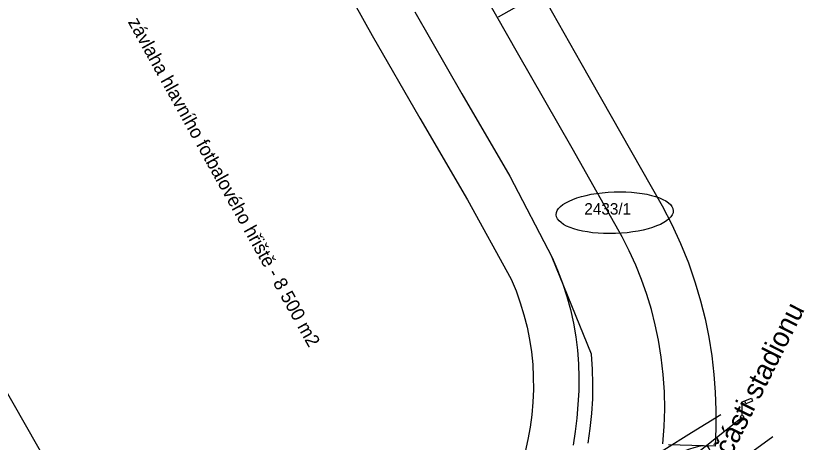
# Model space of a CAD drawing. Extents: x -483721 to -481876, y -1129170 to -1127366.
# Drawn here: x -482396.9 to -482279.7, y -1128190 to -1128126.6 of the extents above; entities that cross this region are included whole.
import ezdxf

# ---------------------------------------------------------------- set-up
doc = ezdxf.new("R2010")
doc.units = 0
for name, color, linetype in [('3 Betonove Plochy', 7, 'Continuous'), ('4 Komunikace', 7, 'Continuous'), ('4 Obrubniky', 7, 'Continuous'), ('kresba', 7, 'Continuous'), ('oblast', 7, 'Continuous'), ('OSTATNI', 7, 'Continuous'), ('Parcelní čísla', 7, 'Continuous'), ('u_návrh_popis', 7, 'Continuous'), ('u_SO_POPIS_1000', 7, 'Continuous')]:
    doc.layers.add(name, color=color, linetype=linetype)

# ---------------------------------------------------------------- blocks, each defined once
blk = doc.blocks.new('LAMPA')
for p, q in [((0, 4.55), (2.79, 5.63)), ((1.17, 3.98), (0.84, 4.87)), ((3.13, 4.71), (1.17, 3.98)), ((2.79, 5.63), (3.13, 4.71)), ((0, 0.52), (0, 4.55))]:
    blk.add_line(p, q)
blk.add_circle((0, 0.02), 0.5)

msp = doc.modelspace()

# ---------------------------------------------------------------- linework, layer by layer
at = {"layer": '3 Betonove Plochy'}
msp.add_lwpolyline([(-482325.12, -1128126.82), (-482318.79, -1128123.2), (-482312.89, -1128133.61), (-482306.96, -1128144.09), (-482300.81, -1128154.85), (-482299.38, -1128157.61), (-482298.08, -1128160.45), (-482296.92, -1128163.34), (-482295.9, -1128166.29), (-482295.11, -1128168.95), (-482294.45, -1128171.65), (-482293.9, -1128174.37), (-482293.46, -1128177.12), (-482293.14, -1128179.88), (-482292.94, -1128182.54), (-482292.84, -1128185.21), (-482292.85, -1128187.88), (-482292.96, -1128190.54), (-482299.89, -1128190.33)], dxfattribs=at)
at = {"layer": '4 Komunikace'}
for points in [[(-482300.71, -1128190.19), (-482300.5, -1128187.62), (-482300.42, -1128185.05), (-482300.47, -1128182.47), (-482300.65, -1128179.91), (-482300.94, -1128177.35), (-482301.36, -1128174.81), (-482301.84, -1128172.52), (-482302.42, -1128170.26), (-482303.09, -1128168.02), (-482303.87, -1128165.82), (-482304.74, -1128163.65), (-482305.7, -1128161.52), (-482306.76, -1128159.44), (-482314.2, -1128146.29), (-482322.32, -1128132.12), (-482330.27, -1128118.08)], [(-482337.58, -1128126.06), (-482330.59, -1128138.24), (-482323.44, -1128150.46), (-482317.17, -1128162.55), (-482316.35, -1128164.43), (-482315.62, -1128166.35), (-482314.98, -1128168.3), (-482314.44, -1128170.27), (-482313.99, -1128172.27), (-482313.63, -1128174.29), (-482313.38, -1128176.29), (-482313.24, -1128178.31), (-482313.18, -1128180.33), (-482313.22, -1128182.35), (-482313.33, -1128184.36), (-482313.51, -1128186.38), (-482313.75, -1128188.39), (-482314.06, -1128190.39)], [(-482311.82, -1128190.08), (-482311.49, -1128187.9), (-482311.26, -1128185.7), (-482311.13, -1128183.5), (-482311.1, -1128181.3), (-482311.17, -1128179.1), (-482311.33, -1128176.9), (-482317.17, -1128162.55)]]:
    msp.add_lwpolyline(points, dxfattribs=at)
at = {"layer": '4 Obrubniky'}
for points in [[(-482350.84, -1128117.09), (-482343.92, -1128129.57), (-482336.82, -1128141.83), (-482329.75, -1128153.97), (-482323.25, -1128165.76), (-482322.53, -1128167.49), (-482321.9, -1128169.26), (-482321.35, -1128171.05), (-482320.88, -1128172.86), (-482320.51, -1128174.7), (-482320.23, -1128176.55), (-482320.05, -1128178.41), (-482319.96, -1128180.27), (-482319.95, -1128182.14), (-482320.03, -1128184.01), (-482320.19, -1128185.87), (-482320.44, -1128187.72), (-482320.76, -1128189.57), (-482321.17, -1128191.39)], [(-482391.56, -1128194.16), (-482399.3, -1128180.6)]]:
    msp.add_lwpolyline(points, dxfattribs=at)
at = {"layer": 'kresba'}
for points in [[(-482386.87, -1128244.71), (-482337.34, -1128245.3), (-482304.59, -1128221.02), (-482292.62, -1128190.48), (-482292.12, -1128185.83), (-482386.87, -1128244.71), (-482292.12, -1128185.83)], [(-482371.94, -1128252.14), (-482352.87, -1128253.17), (-482333.7, -1128247.75), (-482316.47, -1128237.78), (-482302, -1128223.19), (-482292.54, -1128205.83), (-482288.95, -1128186.24), (-482371.94, -1128252.14), (-482288.95, -1128186.24)], [(-482371.94, -1128252.14), (-482347.59, -1128254.37), (-482324.64, -1128248.35), (-482320.83, -1128246.15), (-482296.38, -1128222.8), (-482288.05, -1128206.72), (-482284.38, -1128189.12), (-482371.94, -1128252.14), (-482284.38, -1128189.12)]]:
    msp.add_open_spline(points, degree=3, dxfattribs=at)
at = {"layer": 'oblast'}
msp.add_ellipse((-482307.86, -1128155.88), major_axis=(-8.7, -0.3), ratio=0.355414, dxfattribs=at)

# ---------------------------------------------------------------- block references
at = {"layer": 'OSTATNI', "xscale": 0.5, "yscale": 0.5}
msp.add_blockref('LAMPA', (-482288.95, -1128186.24), dxfattribs=at)

# ---------------------------------------------------------------- texts
at = {"layer": 'Parcelní čísla'}
msp.add_text('2433/1', height=1.7, dxfattribs=at).set_placement((-482312.38, -1128156.16))
at = {"layer": 'u_návrh_popis'}
msp.add_text('závlaha hlavního fotbalového hřiště - 8 500 m2', height=2, rotation=299.0883, dxfattribs=at).set_placement((-482380.24, -1128127.55))
at = {"layer": 'u_SO_POPIS_1000'}
msp.add_text('SO 04 - Odvodnění  JV části stadionu', height=3, rotation=63.3699, dxfattribs=at).set_placement((-482309.67, -1128230.21))

doc.saveas('drawing.dxf')
